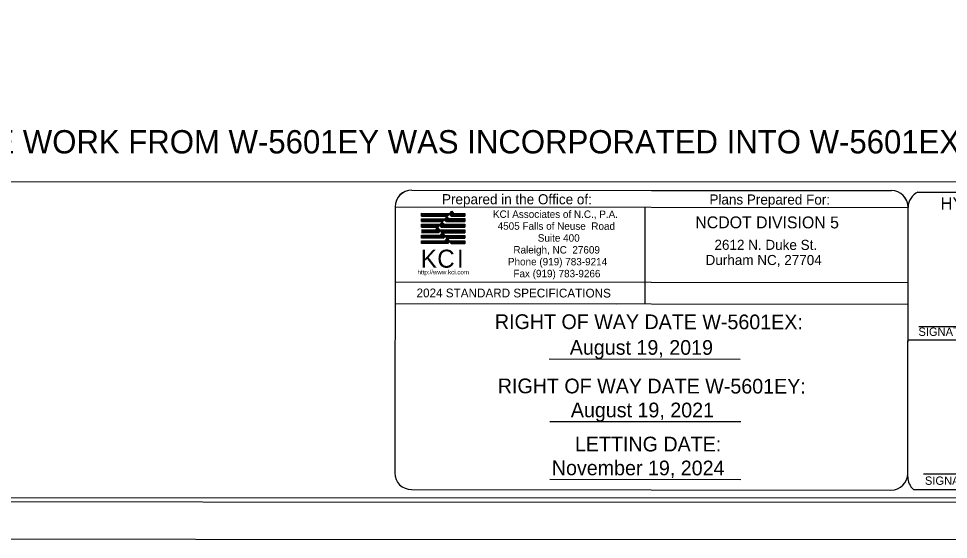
# Model space of a CAD drawing. Extents: x 2105791 to 2114488, y 667759 to 673441.
# Drawn here: x 2109589 to 2112480, y 667759 to 669376 of the extents above; entities that cross this region are included whole.
import ezdxf

# ---------------------------------------------------------------- set-up
doc = ezdxf.new("R2010")
doc.units = 0
for name, color, linetype in [('Old_Level_1', 7, 'Continuous'), ('Sheet Data Field CELL', 7, 'Continuous'), ('Sheet Plot Border Inside CELL', 7, 'Continuous'), ('Sheet Plot Border Outside CELL', 7, 'Continuous'), ('Sheet Title CELL', 7, 'Continuous')]:
    doc.layers.add(name, color=color, linetype=linetype)

msp = doc.modelspace()

# ---------------------------------------------------------------- linework, layer by layer
at = {"layer": 'Old_Level_1'}
for p, q in [((2110842, 668771.6), (2110941, 668771.5)), ((2110842, 668770.9), (2110976.3, 668770.8)), ((2110842, 668770.2), (2110976.3, 668770.1)), ((2110842, 668769.5), (2110976.3, 668769.3)), ((2110842, 668768.8), (2110927.6, 668768.7)), ((2110842, 668768.1), (2110926.9, 668768)), ((2110842, 668767.3), (2110926.1, 668767.2)), ((2110842, 668766.6), (2110925.4, 668766.5)), ((2110842, 668765.9), (2110924.7, 668765.8)), ((2110842, 668765.2), (2110924, 668765.1)), ((2110928.4, 668768.7), (2110976.3, 668768.6)), ((2110929.1, 668768), (2110976.3, 668767.9)), ((2110929.8, 668767.2), (2110976.3, 668767.2)), ((2110930.1, 668772.3), (2110940.4, 668772.3)), ((2110930.5, 668766.5), (2110976.3, 668766.5)), ((2110930.8, 668773), (2110939.8, 668773)), ((2110931.2, 668765.8), (2110976.3, 668765.8)), ((2110931.5, 668773.7), (2110939.2, 668773.7)), ((2110931.8, 668765.1), (2110976.3, 668765)), ((2110932.2, 668774.4), (2110938.6, 668774.4)), ((2110932.8, 668775.1), (2110938, 668775.1)), ((2110933.5, 668775.8), (2110937.4, 668775.8)), ((2110934.2, 668776.6), (2110936.8, 668776.6)), ((2110934.9, 668777.3), (2110936.2, 668777.3)), ((2110841.9, 668737.2), (2110976.2, 668737.1)), ((2110841.9, 668736.5), (2110976.2, 668736.4)), ((2110842, 668764.5), (2110923.3, 668764.4)), ((2110842, 668763.8), (2110922.6, 668763.7)), ((2110842, 668763), (2110921.9, 668762.9)), ((2110842, 668754.4), (2110976.3, 668754.2)), ((2110842, 668753.7), (2110976.3, 668753.5)), ((2110842, 668752.9), (2110976.3, 668752.8)), ((2110842, 668752.2), (2110976.3, 668752.1)), ((2110842, 668751.5), (2110912.5, 668751.4)), ((2110842, 668750.8), (2110911.8, 668750.7)), ((2110842, 668750.1), (2110911, 668750)), ((2110842, 668749.3), (2110910.2, 668749.2)), ((2110842, 668748.6), (2110909.4, 668748.6)), ((2110842, 668747.9), (2110908.6, 668747.8)), ((2110842, 668747.2), (2110907.9, 668747.1)), ((2110842, 668746.5), (2110907.1, 668746.4)), ((2110884.1, 668737.9), (2110976.2, 668737.8)), ((2110899.8, 668738.6), (2110911, 668738.6)), ((2110900.5, 668739.3), (2110910.4, 668739.3)), ((2110901.2, 668740), (2110909.8, 668740)), ((2110901.9, 668740.8), (2110909.2, 668740.8)), ((2110902.6, 668741.5), (2110908.6, 668741.5)), ((2110903.3, 668742.2), (2110908, 668742.2)), ((2110904, 668742.9), (2110907.4, 668742.9)), ((2110904.8, 668743.6), (2110906.8, 668743.6)), ((2110905.5, 668744.3), (2110906.2, 668744.3)), ((2110912.8, 668751.4), (2110976.3, 668751.3)), ((2110913.6, 668750.7), (2110976.3, 668750.6)), ((2110914.3, 668750), (2110976.3, 668749.9)), ((2110914.8, 668755), (2110976.3, 668754.9)), ((2110915, 668749.2), (2110976.3, 668749.2)), ((2110915.5, 668755.8), (2110926.1, 668755.7)), ((2110915.7, 668748.5), (2110976.3, 668748.5)), ((2110916.1, 668756.5), (2110925.4, 668756.5)), ((2110916.5, 668747.8), (2110976.3, 668747.8)), ((2110916.7, 668757.2), (2110924.7, 668757.2)), ((2110917.2, 668747.1), (2110976.3, 668747)), ((2110917.4, 668757.9), (2110923.9, 668757.9)), ((2110917.9, 668746.4), (2110976.3, 668746.3)), ((2110918, 668758.6), (2110923.2, 668758.6)), ((2110918.7, 668759.3), (2110922.5, 668759.3)), ((2110919.4, 668760.1), (2110921.7, 668760.1)), ((2110920, 668760.8), (2110921, 668760.8)), ((2110932.5, 668764.4), (2110976.3, 668764.3)), ((2110933.2, 668763.7), (2110976.3, 668763.6)), ((2110933.9, 668762.9), (2110976.3, 668762.9)), ((2110841.9, 668735.8), (2110976.2, 668735.6)), ((2110841.9, 668735.1), (2110897.3, 668735)), ((2110841.9, 668734.3), (2110896.7, 668734.3)), ((2110841.9, 668733.6), (2110896, 668733.6)), ((2110841.9, 668732.9), (2110895.4, 668732.9)), ((2110841.9, 668732.2), (2110894.8, 668732.1)), ((2110841.9, 668731.5), (2110894.2, 668731.4)), ((2110841.9, 668730.8), (2110893.6, 668730.7)), ((2110841.9, 668730), (2110893, 668730)), ((2110841.9, 668729.3), (2110892.3, 668729.3)), ((2110841.9, 668720.4), (2110885.8, 668720.3)), ((2110841.9, 668719.7), (2110976.2, 668719.5)), ((2110841.9, 668719), (2110976.2, 668718.8)), ((2110841.9, 668718.3), (2110899.2, 668718.2)), ((2110841.9, 668717.5), (2110898.6, 668717.5)), ((2110841.9, 668716.8), (2110898, 668716.8)), ((2110841.9, 668716.1), (2110897.3, 668716.1)), ((2110841.9, 668715.4), (2110896.7, 668715.3)), ((2110841.9, 668714.7), (2110896.1, 668714.6)), ((2110841.9, 668714), (2110895.5, 668713.9)), ((2110841.9, 668713.2), (2110894.8, 668713.2)), ((2110841.9, 668712.5), (2110894.2, 668712.5)), ((2110841.9, 668711.8), (2110893.6, 668711.8)), ((2110893.3, 668711.4), (2110841.9, 668711.5)), ((2110885.8, 668720.3), (2110891.7, 668727.7)), ((2110885.8, 668720.4), (2110898.1, 668720.4)), ((2110886.4, 668721.1), (2110897.5, 668721.1)), ((2110886.9, 668721.8), (2110896.9, 668721.8)), ((2110887.5, 668722.5), (2110896.2, 668722.5)), ((2110888.1, 668723.2), (2110895.6, 668723.2)), ((2110888.7, 668724), (2110895, 668724)), ((2110889.3, 668724.7), (2110894.3, 668724.7)), ((2110889.8, 668725.4), (2110893.7, 668725.4)), ((2110890.4, 668726.1), (2110893.1, 668726.1)), ((2110891, 668726.8), (2110892.4, 668726.8)), ((2110891.6, 668727.5), (2110891.8, 668727.5)), ((2110891.7, 668727.7), (2110898.2, 668720.3)), ((2110899.2, 668718.2), (2110893.3, 668711.4)), ((2110898.2, 668735), (2110976.2, 668734.9)), ((2110898.2, 668720.3), (2110976.2, 668720.2)), ((2110898.9, 668734.3), (2110976.2, 668734.2)), ((2110899.2, 668718.2), (2110976.2, 668718.1)), ((2110906, 668711.6), (2110899.2, 668718.2)), ((2110899.5, 668733.6), (2110976.2, 668733.5)), ((2110900, 668717.5), (2110976.2, 668717.4)), ((2110900.1, 668732.9), (2110976.2, 668732.8)), ((2110900.7, 668732.1), (2110976.2, 668732)), ((2110900.7, 668716.8), (2110976.2, 668716.7)), ((2110901.3, 668731.4), (2110976.2, 668731.3)), ((2110901.5, 668716.1), (2110976.2, 668716)), ((2110902, 668730.7), (2110976.2, 668730.6)), ((2110902.2, 668715.3), (2110976.2, 668715.2)), ((2110902.6, 668730), (2110976.2, 668729.9)), ((2110902.9, 668714.6), (2110976.2, 668714.5)), ((2110903.2, 668729.3), (2110976.2, 668729.2)), ((2110903.7, 668713.9), (2110976.2, 668713.8)), ((2110904.1, 668707.3), (2110909.8, 668707.3)), ((2110904.4, 668713.1), (2110976.2, 668713.1)), ((2110904.7, 668708), (2110909.3, 668708)), ((2110905.1, 668712.4), (2110976.2, 668712.4)), ((2110905.3, 668708.8), (2110908.7, 668708.8)), ((2110905.9, 668711.7), (2110976.2, 668711.7)), ((2110905.9, 668709.5), (2110908.2, 668709.5)), ((2110976.2, 668711.6), (2110906, 668711.6)), ((2110906.5, 668710.2), (2110907.6, 668710.2)), ((2110976.2, 668720.2), (2110976.2, 668711.6)), ((2110841.9, 668703.8), (2110912.6, 668703.7)), ((2110841.9, 668703.1), (2110976.2, 668702.9)), ((2110841.9, 668702.3), (2110976.2, 668702.2)), ((2110841.9, 668701.6), (2110914.8, 668701.6)), ((2110841.9, 668700.9), (2110914.1, 668700.9)), ((2110841.9, 668700.2), (2110913.5, 668700.1)), ((2110841.9, 668699.5), (2110912.9, 668699.4)), ((2110841.9, 668698.8), (2110912.3, 668698.7)), ((2110841.9, 668698), (2110911.6, 668698)), ((2110841.9, 668697.3), (2110911, 668697.3)), ((2110841.9, 668696.6), (2110910.3, 668696.6)), ((2110841.9, 668695.9), (2110909.7, 668695.8)), ((2110841.9, 668695.2), (2110909.1, 668695.1)), ((2110841.9, 668686.5), (2110976.2, 668686.4)), ((2110841.9, 668685.8), (2110976.2, 668685.7)), ((2110841.9, 668685.1), (2110976.2, 668685)), ((2110841.9, 668684.3), (2110929.6, 668684.2)), ((2110841.9, 668683.6), (2110928.9, 668683.5)), ((2110841.9, 668682.9), (2110928.2, 668682.9)), ((2110841.9, 668682.2), (2110927.6, 668682.1)), ((2110841.9, 668681.5), (2110926.9, 668681.4)), ((2110841.9, 668680.8), (2110926.2, 668680.7)), ((2110841.9, 668680), (2110925.5, 668679.9)), ((2110841.9, 668679.3), (2110924.8, 668679.2)), ((2110841.9, 668678.6), (2110924.2, 668678.5)), ((2110901.7, 668704.4), (2110912.1, 668704.4)), ((2110902.3, 668705.2), (2110911.5, 668705.2)), ((2110902.9, 668705.9), (2110911, 668705.9)), ((2110903.5, 668706.6), (2110910.4, 668706.6)), ((2110915, 668701.6), (2110976.2, 668701.5)), ((2110915.5, 668700.9), (2110976.2, 668700.8)), ((2110915.8, 668687.2), (2110927.4, 668687.2)), ((2110916, 668700.1), (2110976.2, 668700)), ((2110916.5, 668699.4), (2110976.2, 668699.3)), ((2110916.5, 668687.9), (2110926.7, 668687.9)), ((2110917, 668698.7), (2110976.2, 668698.6)), ((2110917.1, 668688.6), (2110926, 668688.6)), ((2110917.6, 668697.9), (2110976.2, 668697.9)), ((2110917.9, 668689.3), (2110925.4, 668689.3)), ((2110918.1, 668697.2), (2110976.2, 668697.2)), ((2110918.5, 668690), (2110924.7, 668690)), ((2110918.6, 668696.5), (2110976.2, 668696.5)), ((2110919.1, 668695.8), (2110976.2, 668695.7)), ((2110919.2, 668690.7), (2110924, 668690.7)), ((2110919.6, 668695.1), (2110976.2, 668695)), ((2110919.9, 668691.5), (2110923.3, 668691.5)), ((2110920.6, 668692.2), (2110922.6, 668692.2)), ((2110921.2, 668692.9), (2110922, 668692.9)), ((2110929.8, 668684.2), (2110976.2, 668684.2)), ((2110930.4, 668683.5), (2110976.2, 668683.5)), ((2110931, 668682.8), (2110976.2, 668682.8)), ((2110931.6, 668682.1), (2110976.2, 668682)), ((2110932.2, 668681.4), (2110976.2, 668681.3)), ((2110932.9, 668680.7), (2110976.2, 668680.6)), ((2110933.5, 668679.9), (2110976.2, 668679.9)), ((2110934.1, 668679.2), (2110976.2, 668679.2)), ((2110934.7, 668678.5), (2110976.2, 668678.5)), ((2110935.4, 668677.8), (2110976.2, 668677.7))]:
    msp.add_line(p, q, dxfattribs=at)
for points in [[(2110842, 668771.8), (2110929.6, 668771.7), (2110935.6, 668778), (2110941.3, 668771.2), (2110976.3, 668771.2), (2110976.3, 668762.5), (2110934.2, 668762.6), (2110928, 668769.1), (2110921.7, 668762.7), (2110842, 668762.8)], [(2110841.9, 668738), (2110899.1, 668737.9), (2110905.9, 668744.7), (2110911.6, 668737.9), (2110976.2, 668737.9), (2110976.2, 668728.9), (2110903.4, 668729), (2110897.8, 668735.6), (2110892.1, 668729), (2110841.9, 668729.1)], [(2110842, 668754.8), (2110914.5, 668754.7), (2110920.5, 668761.3), (2110926.7, 668755.2), (2110976.3, 668755.2), (2110976.3, 668746), (2110918.3, 668746), (2110912.7, 668751.6), (2110906.7, 668746), (2110842, 668746.1)], [(2110841.9, 668703.8), (2110901.1, 668703.8), (2110907.1, 668710.8), (2110913, 668703.3), (2110976.2, 668703.2), (2110976.2, 668694.5), (2110920, 668694.6), (2110914.9, 668701.7), (2110908.6, 668694.6), (2110841.9, 668694.7)], [(2110841.9, 668686.8), (2110915.4, 668686.7), (2110921.6, 668693.3), (2110927.8, 668686.7), (2110976.2, 668686.7), (2110976.2, 668677.5), (2110935.6, 668677.5), (2110929.7, 668684.4), (2110923.5, 668677.8), (2110841.9, 668677.9)]]:
    msp.add_lwpolyline(points, close=True, dxfattribs=at)
at = {"layer": 'Sheet Plot Border Inside CELL'}
msp.add_lwpolyline([(2105858.2, 667876.6), (2114463.6, 667875.1), (2114464.5, 673323.4), (2105859.1, 673324.8)], close=True, dxfattribs=at)
at = {"layer": 'Sheet Plot Border Outside CELL'}
msp.add_lwpolyline([(2114487.7, 673439.3), (2105792, 673440.8), (2105791, 667760.7), (2114486.8, 667759.2)], close=True, dxfattribs=at)
at = {"layer": 'Sheet Title CELL'}
for p, q in [((2106989.2, 668870.7), (2114321.7, 668869.5)), ((2110811.7, 668843.9), (2112302, 668842.2)), ((2110811.7, 668843.6), (2112302, 668841.9)), ((2112384.6, 668837.6), (2113441.8, 668837.4)), ((2110759.3, 668791.9), (2110758.4, 667964.2)), ((2110759.3, 668791.6), (2112352.2, 668789.8)), ((2111536.2, 668790.7), (2111535.9, 668490)), ((2112353.3, 667964.2), (2112354.2, 668789.8)), ((2112353.3, 667953.1), (2112354.2, 668789.8)), ((2112352, 668555.8), (2110759, 668557.6)), ((2112354, 668555.8), (2110759, 668557.6)), ((2111446.9, 668490.1), (2110759, 668490.9)), ((2112353.9, 668489.1), (2110759, 668490.9)), ((2111248.1, 668490.4), (2111248.1, 668490.4)), ((2111248.7, 668490.4), (2111248.7, 668490.4)), ((2111248.7, 668490), (2111248.7, 668490)), ((2112387.8, 668420.6), (2113132.7, 668420.5)), ((2112353.8, 668379.4), (2113468.4, 668379.2)), ((2111496.4, 668335.7), (2111496.4, 668335.7)), ((2111832.3, 668318.3), (2111238.3, 668318.9)), ((2111496.7, 668240.2), (2111496.7, 668240.2)), ((2111834.2, 668124.2), (2111240.1, 668124.8)), ((2112401.9, 667963.3), (2113132.6, 667963.1)), ((2111834.2, 667944.2), (2111240.1, 667944.8)), ((2112370.6, 667914.5), (2113416.7, 667914.6))]:
    msp.add_line(p, q, dxfattribs=at)
for points in [[(2110810.6, 667913.7), (2112301, 667912)], [(2106705, 667889.6), (2114347.4, 667888.3)]]:
    msp.add_lwpolyline(points, dxfattribs=at)
for centre, start, end in [((2110811.6, 668791.8), 89.9376, 179.9376), ((2110811.6, 668791.5), 89.9376, 179.9376), ((2112302, 668790.2), 359.9376, 89.9376), ((2112302, 668789.9), 359.9376, 89.9376), ((2112406.5, 668790.1), 114.7561, 179.9376), ((2110810.7, 667966), 179.9376, 269.9376), ((2112301, 667964.3), 269.9376, 359.9376), ((2112405.6, 667953.4), 179.9376, 228.004)]:
    msp.add_arc(centre, 52.3, start, end, dxfattribs=at)

# ---------------------------------------------------------------- texts
at = {"layer": 'Old_Level_1'}
for s, height, rotation, p in [('NOTE: W-5601EY WAS DELETED.  THE WORK FROM W-5601EY WAS INCORPORATED INTO W-5601EX.', 72.352, 360, (2107790.5, 668957.8)), ('KCI Associates of N.C., P.A.', 23.042, 359.9376, (2111063.7, 668757.8)), ('4505 Falls of Neuse  Road ', 23.042, 359.9376, (2111078.3, 668720.9)), (' Suite 400', 23.04, 359.9376, (2111194.5, 668683.9)), ('K', 56, 359.9376, (2110839.5, 668603.1)), ('C', 56, 359.9376, (2110890.5, 668603)), ('I', 56, 359.9376, (2110951.9, 668602.9)), ('Raleigh, NC  27609', 23.042, 359.9376, (2111127.3, 668647.1)), ('Phone (919) 783-9214', 23.042, 359.9376, (2111110.3, 668610.3)), ('http://www.kci.com', 13.893, 359.9376, (2110829.2, 668582.3)), ('Fax (919) 783-9266', 23.042, 359.9376, (2111127.2, 668573.4))]:
    msp.add_text(s, height=height, rotation=rotation, dxfattribs=at).set_placement(p)
at = {"layer": 'Sheet Data Field CELL'}
for s, p in [('August 19, 2019', (2111302.6, 668332.8)), ('August 19, 2021', (2111305.8, 668138.5)), ('November 19, 2024', (2111246.7, 667958.6))]:
    msp.add_text(s, height=45.7, rotation=359.9376, dxfattribs=at).set_placement(p)
at = {"layer": 'Sheet Title CELL'}
for s, height, rotation, p in [('Prepared in the Office of:', 31.333, 359.9376, (2110905.4, 668800.1)), ('Plans Prepared For:', 31.333, 359.9376, (2111736.6, 668799.2)), (' HYDRAULICS ENGINEER', 38.728, 359.9903, (2112440.5, 668783.2)), ('NCDOT DIVISION 5', 36.866, 359.9376, (2111692.8, 668725.5)), ('2612 N. Duke St.', 31.336, 359.9376, (2111752.3, 668658.4)), ('Durham NC, 27704', 31.336, 359.9376, (2111724.7, 668611.4)), ('2024 STANDARD SPECIFICATIONS', 27.192, 359.9376, (2110826.1, 668511)), ('RIGHT OF WAY DATE W-5601EX: ', 45.698, 359.9376, (2111069.6, 668412.6)), ('SIGNATURE:', 25.82, 359.9903, (2112386.4, 668391.2)), ('RIGHT OF WAY DATE W-5601EY:', 45.698, 359.9376, (2111078.7, 668213)), ('LETTING DATE:', 45.698, 359.9376, (2111318.5, 668032.7)), ('SIGNATURE:', 25.82, 359.9903, (2112406.6, 667928.7))]:
    msp.add_text(s, height=height, rotation=rotation, dxfattribs=at).set_placement(p)

doc.saveas('drawing.dxf')
